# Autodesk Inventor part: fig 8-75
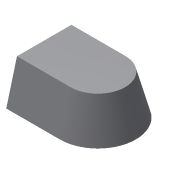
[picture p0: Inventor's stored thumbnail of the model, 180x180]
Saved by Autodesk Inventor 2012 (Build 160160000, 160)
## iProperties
Shininess: 77.0
Length Units: 11269
Angle Units: 11279
Time Units: 11290
Mass Units: 11283
Length Display Precision: 3
Angle Display Precision: 2
Created: 2002-01
Part Number: fig 8-75
Document SubType Name: Modeling
Designer: ***
Density: 1 g/cm^3
Material: Default
Density: 0.0
Volumn: 0.0
Area: 0.0
PropertySet Name: Model Information
Control State: 0
Master: False
Checked Out: False
Author: ***
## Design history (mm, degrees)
sketch "Sketch2"
  geometry: L1 (-19.86, 19.946)-(-19.86, -14.161); L2 (-19.86, -14.161)-(13.729, -14.161); L3 (13.729, 19.946)-(-19.86, 19.946); A1 r 17.054 centre (13.729, 2.893) between (13.729, -14.161) and (13.729, 19.946)
  constraints: 6 end point, 2 point on circle, 2 tangent, 1 centre point, 1 parallel, 1 perpendicular, 1 vertical
extrude "Extrusion2" new body sketch "Sketch2" distance "d6" = 25; taper "d7" = 0 deg
feature "FaceDraft8" dims angle "d14" = 15 deg
body "Solid1"
